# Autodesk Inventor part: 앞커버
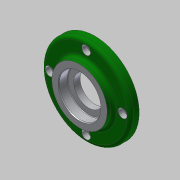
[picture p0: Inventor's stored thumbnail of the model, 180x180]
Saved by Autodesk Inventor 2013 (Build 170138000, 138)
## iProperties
Created: 2019-01
Part Number: 앞커버
Material: 알루미늄 6061
Document SubType Name: Modeling
Designer: mduedu
Density: 1 g/cm^3
Author: mduedu
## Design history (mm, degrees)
sketch "스케치1"
  geometry: L1 (0, 0)-(6, 0); L2 (6, 0)-(6, 25); L3 (6, 25)-(0, 25); L4 (0, 25)-(0, 0); L5 (6, 0)-(14, 0); L6 (14, 0)-(14, 40); L7 (14, 40)-(6, 40); L8 (6, 40)-(6, 0); L9 (14, 0)-(19, 0); L10 (19, 0)-(19, 26); L11 (19, 26)-(14, 26); L12 (14, 26)-(14, 0)
  constraints: 24 end point, 6 parallel, 3 horizontal, 3 perpendicular
  dimensions: "d6" = 80 diameter of L7 L5; "d8" = 50 diameter of L3 L1; "d9" = 52 diameter of L11 L9; "d10" = 5 distance of L10.end L11.end; "d11" = 6 distance of L2.end L3.end; "d12" = 19 distance between parallel lines of L4 L10; "d13" = 8 distance of L6.end L7.end (derived)
revolve "회전1" sketch "스케치1" stored, may be unused: angle "d5" = 90 deg
sketch "스케치2"
  geometry: C1 r 13.5 at (0, 0); 1 further point
  constraints: 1 centre point, 1 coincident
  dimensions: "d14" = 27 diameter of C1
extrude "돌출1" cut sketch "스케치2" stored distance "d15" = 10; taper "d16" = 0 deg
sketch "스케치3" dims "d17" = 66
  geometry: 6 further points
  constraints: 2 vertical alignment, 1 coincident, 7 other
  dimensions: "d20" = 360 deg dimension on point (0, 0) point (0, 33) (derived)
sketch "스케치4"
  geometry: 4 further points
  constraints: 4 other
hole "구멍1" sketch "스케치4" at (-33, 0), (0, -33), (33, 0), (0, 33) diameter "d22" = 4.5; stored, may be unused: countersink angle "d26" = 90 deg, drill point angle "d28" = 0 deg; dims "d23" = 6, "d24" = 8, "d25" = 4.6, "d27" = 8
fillet "모깎기1" dims "d29" = 3
sketch "스케치5"
  geometry: C1 r 19 at (0, 0); 1 further point
  constraints: 1 centre point, 1 coincident
  dimensions: "d30" = 38 diameter of C1
extrude "돌출2" cut sketch "스케치5" distance "d31" = 8.3; taper "d32" = 0 deg
fillet "모깎기2" dims "d33" = 3
chamfer "모따기1" distance "d34" = 0.8; stored, may be unused: second distance "d35" = 2, angle "d36" = 30 deg
fillet "모깎기3" dims "d37" = 0.5
sketch "스케치6"
  geometry: C1 r 22 at (0, 0); 1 further point
  constraints: 1 centre point, 1 coincident
  dimensions: "d38" = 44 diameter of C1
extrude "돌출3" cut sketch "스케치6" distance "d39" = 5; taper "d40" = 0 deg
fillet "모깎기4" dims "d41" = 3
chamfer "모따기2" distance "d42" = 1; stored, may be unused: second distance "d43" = 2, angle "d44" = 30 deg
node "솔리드1"
